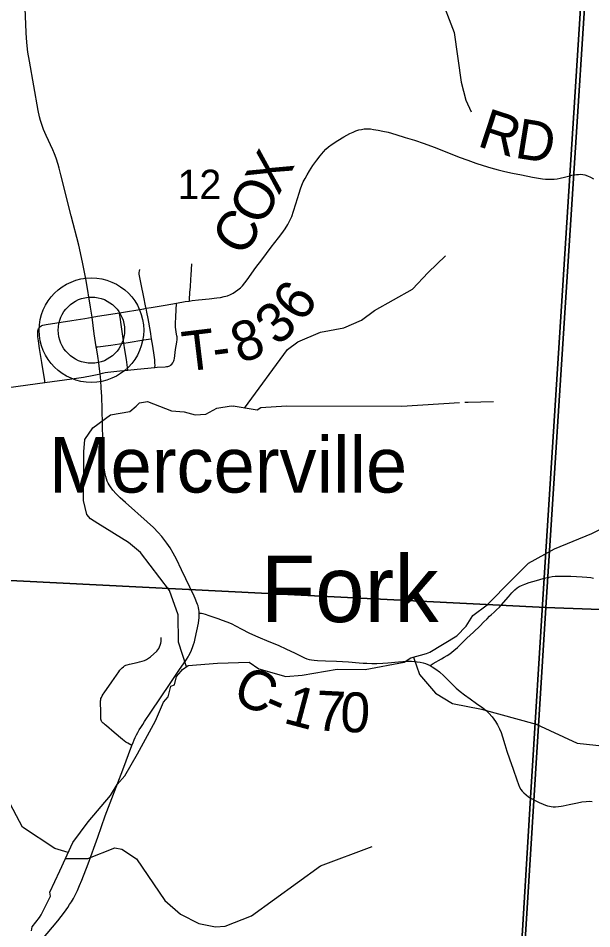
# Model space of a CAD drawing. Extents: x 0 to 34, y 0 to 22.
# Drawn here: x 5.443 to 6.26, y 17.839 to 19.136 of the extents above; entities that cross this region are included whole.
import ezdxf

# ---------------------------------------------------------------- set-up
doc = ezdxf.new("R2010")
doc.units = 0
for name, color, linetype in [('Default', 7, 'Continuous'), ('GM_X_County_Road', 7, 'Continuous'), ('GM_X_County_Road_Text', 7, 'Continuous'), ('GM_X_Minor_River', 7, 'Continuous'), ('GM_X_Minor_River_Text', 7, 'Continuous'), ('GM_X_Section', 7, 'Continuous'), ('GM_X_Section_Text', 7, 'Continuous'), ('GM_X_State_Route', 7, 'Continuous'), ('GM_X_Township_Road', 7, 'Continuous'), ('GM_X_Township_Road_Text', 7, 'Continuous'), ('GM_X_Unincorporated', 7, 'Continuous'), ('GM_X_Unincorporated_Location', 7, 'Continuous'), ('GM_X_Unincorporated_Text', 7, 'Continuous')]:
    doc.layers.add(name, color=color, linetype=linetype)

msp = doc.modelspace()

# ---------------------------------------------------------------- linework, layer by layer
at = {"layer": 'Default'}
msp.add_lwpolyline([(2.1, 19.5179), (2.1, 14.1), (5.687, 14.1), (5.785, 14.1504), (5.9145, 14.1963), (5.9273, 14.1959), (5.9341, 14.3014), (6.0001, 15.328), (6.0418, 15.9539), (6.0633, 16.2368), (6.0901, 16.6706), (6.1151, 17.0743), (6.1723, 18.0255), (6.1917, 18.3385), (6.2282, 18.9116), (6.2536, 19.3066), (5.4875, 19.3459), (4.7013, 19.3856), (4.4284, 19.3984), (3.7007, 19.4348)], close=True, dxfattribs=at)
msp.add_lwpolyline([(8.9, 14.1), (8.9, 19.1797), (8.8731, 19.181), (8.4872, 19.2008), (7.1944, 19.2649), (6.2536, 19.3066), (6.2282, 18.9116), (6.1917, 18.3385), (6.1723, 18.0255), (6.1151, 17.0743), (6.0901, 16.6706), (6.0633, 16.2368)], dxfattribs=at)
at = {"layer": 'GM_X_County_Road'}
for points in [[(5.2338, 18.5668), (5.2347, 18.5673), (5.2417, 18.5702), (5.2489, 18.5731), (5.2548, 18.5753), (5.2604, 18.5773), (5.2663, 18.5791), (5.2721, 18.5807), (5.2944, 18.5866), (5.3313, 18.5957), (5.3374, 18.5971), (5.3434, 18.5983), (5.3496, 18.5995), (5.3561, 18.6006), (5.3639, 18.6017), (5.3728, 18.6029), (5.4287, 18.6099), (5.4807, 18.617), (5.5191, 18.6222), (5.5356, 18.6246), (5.5479, 18.6266), (5.555, 18.6281), (5.5593, 18.6291)], [(5.7005, 18.2884), (5.7038, 18.2882), (5.7058, 18.2879), (5.7089, 18.287), (5.7142, 18.2851), (5.721, 18.2826), (5.727, 18.2806), (5.7332, 18.2786), (5.7399, 18.276), (5.7459, 18.2734), (5.753, 18.2696), (5.7601, 18.2659), (5.7722, 18.2598), (5.7838, 18.2545), (5.7995, 18.248), (5.813, 18.2426), (5.8249, 18.2373), (5.8362, 18.232), (5.8502, 18.2247), (5.8537, 18.2234), (5.8572, 18.2224), (5.8606, 18.2218), (5.864, 18.2214), (5.8689, 18.2209), (5.8803, 18.2203), (5.896, 18.2199), (5.9045, 18.2195), (5.9131, 18.2188), (5.9285, 18.2174), (5.9341, 18.217), (5.9391, 18.2169), (5.9465, 18.2168), (5.9534, 18.2168), (5.9621, 18.2172), (5.9689, 18.2176), (5.9842, 18.2192), (5.9905, 18.2197), (5.9966, 18.22), (5.9998, 18.22), (6.003, 18.2199), (6.007, 18.2196), (6.011, 18.2192), (6.015, 18.2185), (6.0194, 18.2176), (6.0229, 18.2166), (6.0261, 18.2154), (6.0292, 18.214), (6.0324, 18.2121), (6.0375, 18.2087), (6.0425, 18.2048), (6.0488, 18.1989), (6.0589, 18.1889), (6.0621, 18.1858), (6.0666, 18.1816), (6.0723, 18.1767), (6.0782, 18.1721), (6.0863, 18.1663), (6.0956, 18.1597), (6.1043, 18.1536), (6.1091, 18.1497), (6.1131, 18.1458), (6.1175, 18.1407), (6.1201, 18.1374), (6.1226, 18.1339), (6.1255, 18.1291), (6.1284, 18.1237), (6.1304, 18.1186), (6.1326, 18.1121), (6.1356, 18.1015), (6.1387, 18.0916), (6.1423, 18.0809), (6.1476, 18.0663), (6.1527, 18.0512), (6.1552, 18.0444), (6.1568, 18.0407), (6.1587, 18.0372), (6.1606, 18.0347), (6.163, 18.0323), (6.166, 18.0295), (6.1696, 18.0268), (6.1725, 18.025)], [(6.1725, 18.025), (6.1747, 18.0237), (6.179, 18.0213), (6.1847, 18.0186), (6.1904, 18.0161), (6.1936, 18.0148), (6.1967, 18.0139), (6.1992, 18.0133), (6.2019, 18.0129), (6.2048, 18.0126), (6.2079, 18.0126), (6.2123, 18.0129), (6.2159, 18.0133), (6.2191, 18.0139), (6.2276, 18.0158), (6.2395, 18.0184), (6.2456, 18.0196), (6.2517, 18.0203), (6.2558, 18.0204), (6.2601, 18.0202)]]:
    msp.add_lwpolyline(points, dxfattribs=at)
at = {"layer": 'GM_X_Minor_River'}
for points in [[(5.9301, 19.2902), (5.992, 19.2553), (6.0181, 19.2072), (6.0434, 19.169), (6.0635, 19.1155), (6.0738, 19.0446), (6.08, 19.0188), (6.0877, 19.0025)], [(5.7649, 18.5805), (5.8262, 18.664), (5.8409, 18.675), (5.8731, 18.6884), (5.9062, 18.6949), (5.9315, 18.7055), (5.95, 18.7193), (6.0042, 18.7499), (6.0265, 18.7734), (6.0514, 18.7973)], [(5.6822, 18.2121), (5.6711, 18.2468), (5.6704, 18.2859), (5.6582, 18.3208), (5.6168, 18.3746), (5.5998, 18.3888), (5.556, 18.416), (5.5456, 18.4228), (5.5402, 18.429), (5.5358, 18.4489), (5.5361, 18.518), (5.5377, 18.5358), (5.5488, 18.5521), (5.5739, 18.5707), (5.6017, 18.5755), (5.6106, 18.5832), (5.6153, 18.588), (5.6267, 18.5899), (5.661, 18.5763), (5.6792, 18.5753), (5.6945, 18.5707), (5.7097, 18.5717), (5.7254, 18.5803), (5.7459, 18.5834), (5.749, 18.5833)], [(6.0713, 18.5878), (5.989, 18.5825), (5.8249, 18.5832), (5.7882, 18.5806), (5.7828, 18.5773), (5.7486, 18.5833)], [(6.1194, 18.5894), (6.0836, 18.5886), (6.0786, 18.5883)], [(5.4613, 17.836), (5.4624, 17.8417), (5.473, 17.8547), (5.4753, 17.8585), (5.4885, 17.8855), (5.4877, 17.8908), (5.5017, 17.9212), (5.5206, 17.9619), (5.5421, 17.9912), (5.5742, 18.0286), (5.5836, 18.0442), (5.5946, 18.0567), (5.6123, 18.0879), (5.638, 18.1348), (5.6497, 18.1614), (5.6561, 18.1694), (5.6602, 18.1842), (5.6651, 18.1865), (5.6681, 18.1983), (5.6746, 18.2059), (5.6768, 18.2082), (5.6848, 18.2139), (5.7263, 18.217), (5.7717, 18.2187), (5.7853, 18.2092), (5.8239, 18.1983), (5.8473, 18.1998), (5.8968, 18.2087), (5.9369, 18.208), (5.9925, 18.2184), (6.0019, 18.2249), (6.0242, 18.231), (6.0287, 18.2329), (6.0673, 18.2562), (6.0805, 18.2699), (6.0903, 18.2848), (6.1107, 18.3), (6.1458, 18.3358), (6.1696, 18.3594), (6.2067, 18.3801), (6.2596, 18.4018), (6.2936, 18.4186)], [(6.0056, 18.2259), (6.014, 18.201), (6.037, 18.1745), (6.0614, 18.1595), (6.1024, 18.1517), (6.1803, 18.1301), (6.2389, 18.1034), (6.3096, 18.0954), (6.3434, 18.0872), (6.3563, 18.0805), (6.3693, 18.065), (6.3911, 18.0377), (6.4214, 17.9878), (6.4451, 17.9712), (6.4587, 17.9659), (6.5049, 17.9335), (6.5155, 17.9283), (6.5387, 17.9238), (6.5539, 17.9224), (6.6153, 17.9371)], [(5.5139, 17.9476), (5.4945, 17.9531), (5.4488, 17.9836), (5.4046, 18.0661), (5.3855, 18.0873), (5.3382, 18.125), (5.3002, 18.1427)], [(5.51, 17.9391), (5.5416, 17.9389), (5.5803, 17.9543), (5.5901, 17.952), (5.6111, 17.9385), (5.6513, 17.8791), (5.6738, 17.8598), (5.6997, 17.8463), (5.7236, 17.8418), (5.7373, 17.8427), (5.7748, 17.8573), (5.8734, 17.9284), (5.9468, 17.9561)]]:
    msp.add_lwpolyline(points, dxfattribs=at)
at = {"layer": 'GM_X_Section'}
for points in [[(5.2288, 19.368), (6.2595, 19.3129), (6.1942, 18.2962), (5.1578, 18.3486)], [(6.2595, 19.3129), (7.3152, 19.2658), (7.2546, 18.2574), (6.1942, 18.2962)], [(5.1578, 18.3486), (6.1942, 18.2962), (6.1312, 17.2799), (5.0921, 17.3266)], [(6.1942, 18.2962), (7.2546, 18.2574), (7.1862, 17.219), (6.1312, 17.2799)]]:
    msp.add_lwpolyline(points, close=True, dxfattribs=at)
at = {"layer": 'GM_X_State_Route'}
for points in [[(5.6931, 18.3125), (5.6752, 18.3499), (5.668, 18.3651), (5.6634, 18.3739), (5.6589, 18.3814), (5.6543, 18.3881), (5.6471, 18.3975), (5.6421, 18.4031), (5.6352, 18.4103), (5.6265, 18.4184), (5.5952, 18.4458), (5.5879, 18.4525), (5.5823, 18.4582), (5.5774, 18.4637), (5.574, 18.4681), (5.5722, 18.4709), (5.5706, 18.4737), (5.5695, 18.4764), (5.5683, 18.4797), (5.5673, 18.4832), (5.5664, 18.4866), (5.5655, 18.492), (5.5647, 18.4982), (5.5639, 18.5074), (5.5633, 18.5223), (5.563, 18.5353), (5.5621, 18.579), (5.5616, 18.5967), (5.5609, 18.6091), (5.5602, 18.6197), (5.5593, 18.6291), (5.5583, 18.6365), (5.5572, 18.6449), (5.5558, 18.6543), (5.5544, 18.6632), (5.5538, 18.6675), (5.551, 18.6863), (5.5477, 18.7099), (5.5457, 18.7243), (5.5392, 18.7622), (5.5341, 18.7884), (5.5287, 18.8126), (5.5179, 18.8541), (5.5034, 18.9124), (5.5009, 18.922), (5.4994, 18.9274), (5.4965, 18.9363), (5.4941, 18.9427), (5.4917, 18.9484), (5.4822, 18.9687), (5.4786, 18.9772), (5.476, 18.9841), (5.4742, 18.99), (5.4729, 18.9954), (5.471, 19.0044), (5.4585, 19.0743), (5.4563, 19.0875), (5.4552, 19.0961), (5.4543, 19.1071), (5.4538, 19.1153), (5.4533, 19.1272), (5.4525, 19.1496)], [(5.6845, 18.2262), (5.6856, 18.2281), (5.6884, 18.2334), (5.6908, 18.2392), (5.6924, 18.2437), (5.6937, 18.2476), (5.6948, 18.2521), (5.6992, 18.274), (5.6999, 18.2782), (5.7003, 18.2818), (5.7005, 18.2851), (5.7005, 18.2884), (5.7003, 18.2909), (5.6999, 18.2935), (5.6995, 18.2961), (5.6989, 18.2986), (5.6981, 18.3008), (5.6972, 18.3032), (5.6948, 18.309), (5.6931, 18.3125)], [(5.4763, 17.823), (5.4989, 17.85), (5.5085, 17.8625), (5.5131, 17.8692), (5.5158, 17.8732), (5.5184, 17.8774), (5.5211, 17.8821), (5.524, 17.8875), (5.527, 17.8935), (5.53, 17.9003), (5.5334, 17.9082), (5.5421, 17.9314), (5.5558, 17.9694), (5.5666, 17.9997), (5.5916, 18.0654), (5.6045, 18.1001), (5.6062, 18.1041), (5.6079, 18.1078), (5.6094, 18.1112), (5.6112, 18.1149), (5.613, 18.1184), (5.615, 18.122), (5.6172, 18.1257), (5.6199, 18.1299), (5.6226, 18.1341), (5.6314, 18.1475), (5.6589, 18.1883), (5.6714, 18.2068), (5.6823, 18.2225), (5.6845, 18.2262)]]:
    msp.add_lwpolyline(points, dxfattribs=at)
at = {"layer": 'GM_X_Township_Road'}
for points in [[(5.5867, 18.7161), (5.6217, 18.722), (5.6248, 18.7225), (5.6321, 18.7238), (5.6518, 18.7272), (5.6681, 18.73), (5.6805, 18.7321), (5.6859, 18.7328), (5.6903, 18.7334), (5.6994, 18.7345), (5.7147, 18.736), (5.7255, 18.7373), (5.7309, 18.7381), (5.7361, 18.7392), (5.7406, 18.7405), (5.7449, 18.7422), (5.7487, 18.7442), (5.7523, 18.7464), (5.7556, 18.7488), (5.759, 18.7517), (5.762, 18.7547), (5.7653, 18.7586), (5.7688, 18.7633), (5.7809, 18.7806), (5.7894, 18.7917), (5.8028, 18.8094), (5.8135, 18.8228), (5.8183, 18.829), (5.8228, 18.8356), (5.8266, 18.8417), (5.8283, 18.8445), (5.8297, 18.8474), (5.8311, 18.8505), (5.8323, 18.8534), (5.8349, 18.8607), (5.8382, 18.8711), (5.8427, 18.8863), (5.8446, 18.8925), (5.8467, 18.8977), (5.8487, 18.9025), (5.8513, 18.9076), (5.8541, 18.9127), (5.8575, 18.9184), (5.8625, 18.9259), (5.8678, 18.9333), (5.8726, 18.9396), (5.8773, 18.9454), (5.8807, 18.949), (5.8844, 18.9524), (5.8899, 18.9565), (5.8977, 18.9616), (5.9064, 18.9668), (5.9152, 18.9714), (5.9197, 18.9736), (5.9236, 18.9752), (5.9276, 18.9765), (5.9316, 18.9773), (5.9355, 18.9779), (5.9398, 18.978), (5.9443, 18.9779), (5.9489, 18.9774), (5.9553, 18.9763), (5.962, 18.975), (5.9695, 18.9732), (5.9807, 18.97), (5.9936, 18.966), (6.0071, 18.9618), (6.0208, 18.9571), (6.0352, 18.9518), (6.0554, 18.944), (6.0709, 18.938), (6.083, 18.9335), (6.0944, 18.9294), (6.1051, 18.9259), (6.1158, 18.9227), (6.1264, 18.9198), (6.1359, 18.9174), (6.1466, 18.915), (6.1597, 18.9124), (6.1751, 18.9094), (6.1894, 18.9071), (6.1939, 18.9066), (6.1978, 18.9064), (6.2022, 18.9064), (6.2062, 18.9065), (6.2105, 18.907), (6.2145, 18.9077), (6.2208, 18.9091), (6.2284, 18.9111)], [(6.2284, 18.9111), (6.2314, 18.9119), (6.2349, 18.9126), (6.2379, 18.9131), (6.2409, 18.9133), (6.2439, 18.9134), (6.2468, 18.9131), (6.2499, 18.9125), (6.2536, 18.9112), (6.2577, 18.9093), (6.2623, 18.9069)], [(5.6895, 18.786), (5.6886, 18.7696), (5.6882, 18.7638), (5.6873, 18.7524), (5.6867, 18.7455), (5.686, 18.7344), (5.6859, 18.7328)], [(5.6248, 18.7225), (5.6245, 18.7236), (5.6209, 18.7406), (5.618, 18.7547), (5.6158, 18.7663), (5.6153, 18.7689), (5.6151, 18.7712), (5.615, 18.7733), (5.6152, 18.7753), (5.6157, 18.778)], [(5.6374, 18.6384), (5.6407, 18.6386), (5.6521, 18.6393), (5.654, 18.6395), (5.6556, 18.6398), (5.657, 18.6401), (5.6584, 18.6408), (5.6597, 18.6416), (5.6612, 18.6428), (5.6627, 18.6448), (5.6635, 18.6459), (5.6642, 18.6475), (5.6649, 18.6493), (5.6653, 18.6512), (5.6668, 18.6637), (5.6684, 18.6742), (5.669, 18.6782), (5.6691, 18.6795), (5.669, 18.6808), (5.6689, 18.682), (5.6687, 18.6831), (5.6676, 18.6883), (5.6669, 18.6927), (5.6667, 18.6951), (5.6666, 18.6975), (5.6666, 18.701), (5.6672, 18.7104), (5.6681, 18.73)], [(5.5477, 18.7099), (5.5554, 18.7113), (5.5651, 18.7129), (5.5867, 18.7161)], [(5.5593, 18.6291), (5.5626, 18.6301), (5.5664, 18.6309), (5.5703, 18.6315), (5.5745, 18.632), (5.5871, 18.6334), (5.5985, 18.6345), (5.6119, 18.6359), (5.6374, 18.6384), (5.6375, 18.6413), (5.6374, 18.6445), (5.6371, 18.6492), (5.6362, 18.6558), (5.6342, 18.6685), (5.6325, 18.6792), (5.631, 18.6893), (5.6278, 18.7081), (5.6259, 18.717), (5.6248, 18.7225)], [(5.5985, 18.6345), (5.5967, 18.6496), (5.5946, 18.6633), (5.593, 18.6729), (5.5925, 18.676), (5.5891, 18.6993), (5.5876, 18.7097), (5.5868, 18.7152), (5.5867, 18.7161)], [(5.4756, 18.6976), (5.4764, 18.698), (5.4778, 18.6985), (5.4802, 18.6992), (5.4822, 18.6995), (5.5189, 18.7052), (5.5373, 18.7079), (5.5425, 18.7088), (5.5477, 18.7099)], [(5.4807, 18.617), (5.4803, 18.6194), (5.4763, 18.6455), (5.473, 18.6655), (5.4713, 18.6763), (5.4705, 18.682), (5.4703, 18.6864), (5.4707, 18.6903), (5.4717, 18.6935), (5.4727, 18.6953), (5.4736, 18.6963), (5.4747, 18.6972), (5.4756, 18.6976)], [(5.5538, 18.6675), (5.5562, 18.6678), (5.5746, 18.6702), (5.5869, 18.6719), (5.593, 18.6729), (5.5992, 18.6738), (5.6213, 18.6775), (5.628, 18.6785), (5.6325, 18.6792)], [(6.0292, 18.214), (6.0335, 18.2165), (6.0456, 18.2234), (6.0494, 18.2256), (6.0536, 18.2282), (6.0573, 18.2306), (6.0632, 18.2351), (6.0683, 18.2396), (6.0746, 18.2456), (6.0785, 18.2495), (6.0817, 18.2525), (6.0912, 18.2613), (6.1005, 18.2701), (6.1056, 18.2755), (6.1104, 18.2804), (6.1139, 18.2839), (6.1162, 18.2861), (6.1205, 18.2896), (6.124, 18.2929), (6.128, 18.297), (6.1306, 18.2996), (6.141, 18.3118), (6.1456, 18.3173), (6.1498, 18.3215), (6.1535, 18.3245), (6.1563, 18.3261), (6.1595, 18.3276), (6.1642, 18.3296), (6.1705, 18.3318), (6.1807, 18.335), (6.1902, 18.3376), (6.1919, 18.338)], [(6.1919, 18.338), (6.199, 18.3398), (6.2034, 18.3406), (6.2073, 18.3409), (6.2107, 18.3411), (6.2154, 18.341), (6.2298, 18.3408), (6.2458, 18.3403), (6.2526, 18.3398), (6.2581, 18.339), (6.2623, 18.3382)], [(5.6045, 18.1001), (5.5989, 18.103), (5.5961, 18.1046), (5.5936, 18.1064), (5.5911, 18.1083), (5.5794, 18.1185), (5.5684, 18.1281), (5.5665, 18.1295), (5.5648, 18.1307), (5.5634, 18.1318), (5.5623, 18.133), (5.5616, 18.1338), (5.5611, 18.1347), (5.5606, 18.1361), (5.5603, 18.1376), (5.5602, 18.1395), (5.5601, 18.1416), (5.5602, 18.1503), (5.5597, 18.1593), (5.5597, 18.1614), (5.5599, 18.1633), (5.5601, 18.165), (5.5605, 18.1666), (5.5611, 18.1681), (5.5623, 18.1706), (5.5636, 18.1728), (5.565, 18.1749), (5.5757, 18.1904), (5.5859, 18.2049), (5.5874, 18.207), (5.5889, 18.2087), (5.5907, 18.2105), (5.5924, 18.212), (5.594, 18.2132), (5.5958, 18.2141), (5.5978, 18.2148), (5.6009, 18.2157), (5.612, 18.218), (5.6152, 18.2188), (5.6191, 18.2199), (5.6224, 18.2211), (5.6254, 18.2225), (5.6282, 18.2241), (5.6312, 18.2263), (5.64, 18.2343), (5.6415, 18.2362), (5.643, 18.2382), (5.644, 18.2402), (5.6449, 18.2427), (5.6456, 18.2455), (5.646, 18.2482), (5.6461, 18.2509), (5.6461, 18.2535)]]:
    msp.add_lwpolyline(points, dxfattribs=at)
at = {"layer": 'GM_X_Unincorporated'}
for radius in [0.0744, 0.0472]:
    msp.add_circle((5.5469, 18.6914), radius, dxfattribs=at)
at = {"layer": 'GM_X_Unincorporated_Location'}
msp.add_line((5.5469, 18.6914), (5.5469, 18.6914), dxfattribs=at)

# ---------------------------------------------------------------- texts
at = {"layer": 'GM_X_County_Road_Text'}
for s, rotation, p in [('C', 336.0016, (5.7452, 18.1641)), ('1', 345.0845, (5.8186, 18.1326)), ('7', 357.1207, (5.8653, 18.1216)), ('0', 356.7979, (5.9001, 18.1199)), ('-', 336.7539, (5.7886, 18.1448))]:
    msp.add_text(s, height=0.0568, rotation=rotation, dxfattribs=at).set_placement(p)
at = {"layer": 'GM_X_Minor_River_Text'}
msp.add_text('Fork', height=0.0947, rotation=359.9962, dxfattribs=at).set_placement((5.7882, 18.2757))
at = {"layer": 'GM_X_Section_Text'}
msp.add_text('12', height=0.04186, rotation=0, dxfattribs=at).set_placement((5.6695, 18.878))
at = {"layer": 'GM_X_Township_Road_Text'}
for s, rotation, p in [('R', 341.8292, (6.0948, 18.9541)), ('D', 350.8483, (6.1485, 18.9373)), ('X', 62.0664, (5.8135, 18.8822)), ('O', 62.6275, (5.7906, 18.8379)), ('C', 57.9501, (5.7633, 18.7939)), ('6', 53.6809, (5.8465, 18.7002)), ('3', 41.9178, (5.8119, 18.6674)), ('8', 19.4828, (5.7582, 18.6434)), ('T', 6.8885, (5.6796, 18.6322)), ('-', 7.4441, (5.7224, 18.6374))]:
    msp.add_text(s, height=0.0568, rotation=rotation, dxfattribs=at).set_placement(p)
at = {"layer": 'GM_X_Unincorporated_Text'}
msp.add_text('Mercerville', height=0.078977, rotation=0, dxfattribs=at).set_placement((5.4862, 18.4601))

doc.saveas('drawing.dxf')
